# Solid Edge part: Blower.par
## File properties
Author: CADCIM
Template: NORMENG.PAR
Last saved by: CADCIM
Revision: 15
Application: Solid Edge
Accuracy: 0.99
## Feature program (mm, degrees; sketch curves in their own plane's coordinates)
sketch for "unnamed RevolvedProtrusion 1" #1 plane through (0, 0, 0) normal (0, -1, 0) x-axis (1, 0, 0)
  line (0, 171.45) -> (139.7, 171.45)
  line (139.7, 171.45) -> (139.7, 165.1)
  line (139.7, 165.1) -> (0, 165.1)
  line (0, 165.1) -> (0, 171.45)
sketch for "unnamed RevolvedProtrusion 1" #2 plane through (0, 0, 0) normal (0, -1, 0) x-axis (1, 0, 0)
  line (0, 0) -> (0, 0)
  line (0, 0) -> (0, 0)
  line (139.7, 0) -> (139.7, -12.7)
  line (139.7, -12.7) -> (38.1, -12.7)
  line (38.1, -12.7) -> (38.1, -76.2)
  line (38.1, -76.2) -> (0, -76.2)
  line (0, -76.2) -> (0, 0)
  line (0, 0) -> (139.7, 0)
  dimension (linear) = 38.1
  dimension (linear) = 139.7
revolve "unnamed RevolvedProtrusion 1" add finite 360 deg
sketch for "unnamed Protrusion 1" plane through (0, 0, 0) normal (0, 0, 1) x-axis (1, 0, 0)
  line (76.708, 0) -> (139.7, 0)
  line (127.6948, -46.4771) -> (131.2751, -47.7802)
  line (76.708, -6.35) -> (135.0219, -6.35)
  line (76.708, 0) -> (76.708, -6.35)
  dimension (linear) = 127.6948
  dimension (linear) = 76.708
extrude "unnamed Protrusion 1" add through along +normal
pattern "unnamed Pattern 1" of "unnamed Protrusion 1"
extrude "unnamed Protrusion 2" add through
extrude "unnamed Protrusion 3" add through
extrude "unnamed Protrusion 4" add through
extrude "unnamed Protrusion 5" add through
extrude "unnamed Protrusion 6" add through
sketch for "unnamed Hole 1" plane through (0, 0, -76.2) normal (0, 0, -1) x-axis (1, 0, 0)
hole "unnamed Hole 1" through
sketch for "ExtrudedCutout_1" plane through (0, 0, 171.45) normal (0, 0, 1) x-axis (0, -1, 0)
extrude "ExtrudedCutout_1" cut finite 6.35 along -normal
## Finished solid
Body 1: solid body, 50 faces, 139 edges, 84 vertices.
  Faces by surface: plane 40, cylinder 10
  Edges by curve: line 96, circle 43
Bounding box of the edges (mm): 279.400 x 279.400 x 247.650, from (-139.7, -139.7, -76.2) to (139.7, 139.7, 171.45).
Cylindrical faces by radius (mm): R19.05 x1, R38.1 x1, R101.6 x1, R131.6115 x6, R139.7 x1
Planar faces by outward normal: +x 1, +y 2, +z 8, -x 1, -y 2, -z 8, oblique 18
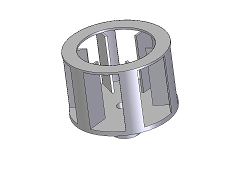
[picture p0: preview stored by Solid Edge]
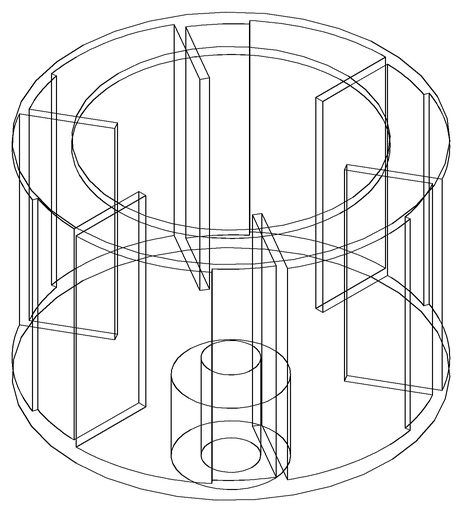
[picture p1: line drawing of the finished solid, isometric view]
